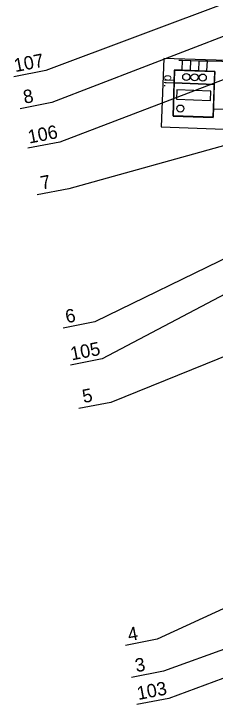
# Model space of a CAD drawing. Extents: x -545736 to -544888, y -1122892 to -1119128.
# Drawn here: x -545184.6 to -545156.5, y -1122499.8 to -1122403 of the extents above; entities that cross this region are included whole.
import ezdxf

# ---------------------------------------------------------------- set-up
doc = ezdxf.new("R2010")
doc.units = 0
for name, color, linetype in [('so180602', 7, 'Continuous'), ('Vrstva 13', 7, 'Continuous'), ('Vrstva 16_plochy', 7, 'Continuous'), ('Vrstva 43', 7, 'Continuous'), ('Vrstva 44', 7, 'Continuous'), ('Vrstva 63', 7, 'Continuous')]:
    doc.layers.add(name, color=color, linetype=linetype)

msp = doc.modelspace()

# ---------------------------------------------------------------- linework, layer by layer
at = {"layer": 'Vrstva 13'}
for p, q in [((-545162.14, -1122410.84), (-545162.14, -1122410.84)), ((-545156.543, -1122411.047), (-545156.543, -1122411.047)), ((-545162.201, -1122412.639), (-545156.605, -1122412.846)), ((-545156.605, -1122412.846), (-545162.201, -1122412.639)), ((-545162.356, -1122417.234), (-545162.356, -1122417.234)), ((-545156.764, -1122417.418), (-545156.764, -1122417.418))]:
    msp.add_line(p, q, dxfattribs=at)
for points in [[(-545162.14, -1122410.84), (-545162.356, -1122417.234), (-545156.764, -1122417.418), (-545156.543, -1122411.047)], [(-545156.764, -1122417.418), (-545162.356, -1122417.234), (-545162.201, -1122412.639), (-545162.201, -1122412.639), (-545162.14, -1122410.84), (-545156.543, -1122411.047), (-545156.605, -1122412.846), (-545156.605, -1122412.846)], [(-545161.824, -1122413.603), (-545161.862, -1122414.921), (-545157.134, -1122415.072), (-545157.063, -1122413.793)]]:
    msp.add_lwpolyline(points, close=True, dxfattribs=at)
at = {"layer": 'Vrstva 16_plochy'}
msp.add_lwpolyline([(-545154.889, -1122409.491), (-545163.658, -1122409.205), (-545164.003, -1122418.764), (-545155.239, -1122419.077)], dxfattribs=at)
msp.add_lwpolyline([(-545162.165, -1122410.811), (-545162.364, -1122417.268), (-545156.735, -1122417.468), (-545156.51, -1122411.022)], close=True, dxfattribs=at)
at = {"layer": 'Vrstva 43'}
for centre in [(-545160.515, -1122411.801), (-545159.358, -1122411.847), (-545158.213, -1122411.885), (-545161.339, -1122416.22)]:
    msp.add_circle(centre, 0.5, dxfattribs=at)
at = {"layer": 'Vrstva 44'}
for p, q in [((-545161.075, -1122410.866), (-545161.04, -1122409.449)), ((-545159.934, -1122410.853), (-545159.873, -1122409.474)), ((-545158.777, -1122410.936), (-545158.718, -1122409.518)), ((-545157.636, -1122410.952), (-545157.567, -1122409.551))]:
    msp.add_line(p, q, dxfattribs=at)
for points in [[(-545161.563, -1122409.448), (-545161.04, -1122409.449), (-545159.873, -1122409.474), (-545158.718, -1122409.518), (-545157.567, -1122409.551), (-545155.535, -1122409.595), (-545151.035, -1122409.842), (-545150.699, -1122409.811), (-545150.354, -1122409.803), (-545117.558, -1122408.854), (-545117.209, -1122408.632), (-545117.207, -1122408.356), (-545114.472, -1122375.479)], [(-545053.287, -1122633.279), (-545063.238, -1122586.146), (-545063.248, -1122585.919), (-545063.296, -1122585.762), (-545072.411, -1122534.849), (-545072.406, -1122534.601), (-545072.52, -1122534.494), (-545080.043, -1122501.027), (-545080.093, -1122500.849), (-545080.193, -1122500.397), (-545087.505, -1122464.21), (-545087.659, -1122463.509), (-545087.757, -1122463.363), (-545099.069, -1122419.052), (-545099.193, -1122418.695), (-545099.586, -1122418.621), (-545116.487, -1122418.299), (-545117.079, -1122418.156), (-545117.605, -1122418.155), (-545149.644, -1122416.388), (-545150.026, -1122416.395), (-545150.307, -1122416.258), (-545156.662, -1122416.357)]]:
    msp.add_lwpolyline(points, dxfattribs=at)
at = {"layer": 'Vrstva 63'}
for p, q in [((-545127.289, -1122391.077), (-545180.147, -1122410.901)), ((-545117.157, -1122391.345), (-545179.271, -1122415.379)), ((-545105.11, -1122393.061), (-545178.191, -1122420.898)), ((-545180.147, -1122410.901), (-545184.591, -1122411.766)), ((-545099.334, -1122412.581), (-545172.254, -1122451.231)), ((-545127.956, -1122413.772), (-545176.91, -1122427.443)), ((-545108.468, -1122414.355), (-545173.267, -1122446.057)), ((-545179.271, -1122415.379), (-545183.715, -1122416.243)), ((-545178.191, -1122420.898), (-545182.635, -1122421.762)), ((-545176.91, -1122427.443), (-545181.354, -1122428.307)), ((-545128.603, -1122440.164), (-545171.063, -1122457.317)), ((-545173.267, -1122446.057), (-545177.711, -1122446.921)), ((-545172.254, -1122451.231), (-545176.698, -1122452.095)), ((-545171.063, -1122457.317), (-545175.507, -1122458.181)), ((-545129.491, -1122474.174), (-545164.575, -1122490.465)), ((-545117.725, -1122478.283), (-545163.698, -1122494.946)), ((-545135.865, -1122488.687), (-545162.956, -1122498.738)), ((-545164.575, -1122490.465), (-545169.019, -1122491.329)), ((-545163.698, -1122494.946), (-545168.142, -1122495.81)), ((-545162.956, -1122498.738), (-545167.4, -1122499.602))]:
    msp.add_line(p, q, dxfattribs=at)

# ---------------------------------------------------------------- texts
at = {"layer": 'so180602'}
for s, p in [('107', (-545184.389, -1122411.127)), ('8', (-545183.098, -1122415.554)), ('106', (-545182.446, -1122421.126)), ('7', (-545180.692, -1122427.563)), ('6', (-545177.208, -1122446.255)), ('105', (-545176.51, -1122451.459)), ('5', (-545174.844, -1122457.424)), ('4', (-545168.5, -1122490.749)), ('3', (-545167.473, -1122495.082)), ('103', (-545167.212, -1122498.966))]:
    msp.add_text(s, height=1.875, rotation=10.99553, dxfattribs=at).set_placement(p)
at = {"layer": 'Vrstva 16_plochy'}
msp.add_text('dl.', height=1.25, rotation=267.933, dxfattribs=at).set_placement((-545163.562, -1122411.472))

doc.saveas('drawing.dxf')
